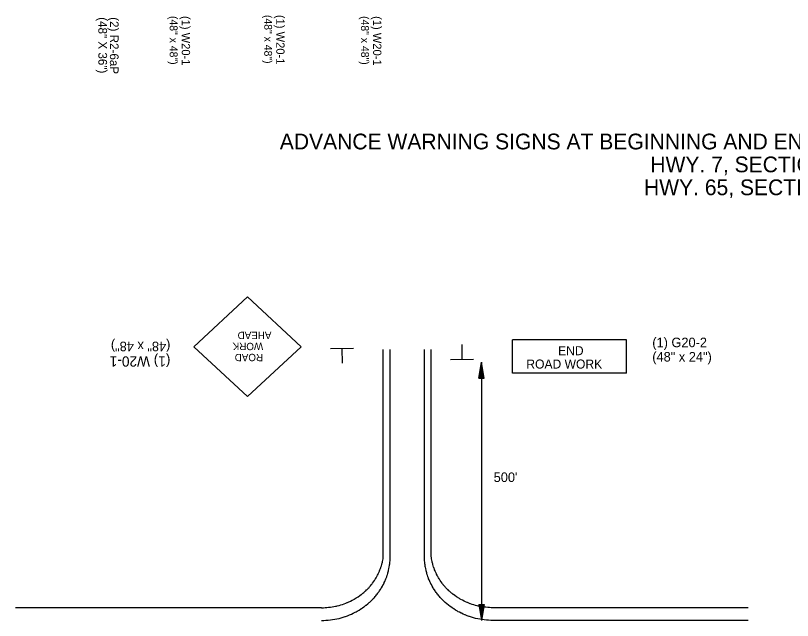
# Model space of a CAD drawing. Extents: x 32485 to 39285, y 55121 to 58033.
# Drawn here: x 37987 to 38508, y 56996 to 57401 of the extents above; entities that cross this region are included whole.
import ezdxf

# ---------------------------------------------------------------- set-up
doc = ezdxf.new("R2010")
doc.units = 0
for name, color, linetype in [('Default', 7, 'Continuous'), ('R_Border', 7, 'Continuous'), ('R_Draft', 7, 'Continuous'), ('R_Proposed Road', 7, 'Continuous'), ('SHET_Stamp-Prelim', 7, 'Continuous')]:
    doc.layers.add(name, color=color, linetype=linetype)

msp = doc.modelspace()

# ---------------------------------------------------------------- linework, layer by layer
at = {"layer": 'R_Border'}
for p, q in [((38106.85, 57178.9), (38142.77, 57212.26)), ((38142.77, 57212.26), (38178.71, 57178.9)), ((38396.7, 57183.42), (38320.4, 57183.42)), ((38320.4, 57161.14), (38320.4, 57183.42)), ((38396.7, 57161.14), (38396.7, 57183.42)), ((38106.85, 57178.9), (38142.77, 57145.5)), ((38142.77, 57145.5), (38178.71, 57178.9)), ((38286.54, 57170.46), (38286.5, 57180.3)), ((38198.26, 57177.77), (38213.78, 57178.01)), ((38205.98, 57177.68), (38206.16, 57167.84)), ((38294.27, 57170.28), (38278.75, 57170.21)), ((38396.7, 57161.14), (38320.4, 57161.14))]:
    msp.add_line(p, q, dxfattribs=at)
at = {"layer": 'R_Proposed Road'}
for p, q in [((38297.86, 57157.79), (38299.59, 57168.47)), ((38299.59, 57168.47), (38299.59, 56995.58)), ((38301.31, 57157.79), (38299.59, 57168.47)), ((38298.15, 57157.79), (38299.59, 57166.69)), ((38298.44, 57157.79), (38299.59, 57164.85)), ((38298.73, 57157.79), (38299.59, 57163.07)), ((38301.02, 57157.79), (38299.59, 57166.69)), ((38300.73, 57157.79), (38299.59, 57164.85)), ((38300.44, 57157.79), (38299.59, 57163.07)), ((38297.86, 57157.79), (38301.31, 57157.79)), ((38299.03, 57157.79), (38299.59, 57161.27)), ((38299.32, 57157.79), (38299.59, 57159.48)), ((38300.15, 57157.79), (38299.59, 57161.27)), ((38299.86, 57157.79), (38299.59, 57159.48)), ((38297.86, 57006.26), (38299.59, 56995.58)), ((38297.86, 57006.26), (38301.31, 57006.26)), ((38298.15, 57006.26), (38299.59, 56997.36)), ((38298.44, 57006.26), (38299.59, 56999.2)), ((38298.73, 57006.26), (38299.59, 57000.98)), ((38299.03, 57006.26), (38299.59, 57002.79)), ((38299.32, 57006.26), (38299.59, 57004.57)), ((38301.31, 57006.26), (38299.59, 56995.58)), ((38300.15, 57006.26), (38299.59, 57002.79)), ((38300.73, 57006.26), (38299.59, 56999.2)), ((38301.02, 57006.26), (38299.59, 56997.36)), ((38300.44, 57006.26), (38299.59, 57000.98)), ((38299.86, 57006.26), (38299.59, 57004.57))]:
    msp.add_line(p, q, dxfattribs=at)
at = {"layer": 'SHET_Stamp-Prelim'}
for p, q in [((38233.75, 57136.01), (38233.75, 57177.09)), ((38238.35, 57135.98), (38238.35, 57177.09)), ((38261.32, 57135.98), (38261.32, 57177.09)), ((38265.92, 57135.98), (38265.92, 57177.09))]:
    msp.add_line(p, q, dxfattribs=at)
for points in [[(38192.39, 56995.58), (38193.86, 56995.6), (38195.33, 56995.67), (38196.8, 56995.78), (38198.27, 56995.93), (38199.63, 56996.11), (38199.72, 56996.13), (38201.18, 56996.37), (38202.62, 56996.65), (38204.05, 56996.98), (38204.86, 56997.18), (38205.47, 56997.35), (38206.87, 56997.76), (38208.26, 56998.21), (38208.38, 56998.25), (38209.64, 56998.7), (38210.99, 56999.24), (38211.19, 56999.32), (38212.33, 56999.81), (38213.57, 57000.38), (38213.65, 57000.42), (38214.94, 57001.08), (38215.65, 57001.45), (38216.21, 57001.77), (38217.46, 57002.5), (38217.5, 57002.52), (38218.68, 57003.26), (38219.18, 57003.59), (38219.88, 57004.06), (38220.71, 57004.66), (38221.04, 57004.9), (38222.12, 57005.72), (38222.18, 57005.77), (38223.29, 57006.67), (38223.43, 57006.79), (38224.36, 57007.61), (38224.64, 57007.86), (38224.89, 57008.09), (38225.4, 57008.58), (38225.76, 57008.93), (38226.41, 57009.58), (38226.81, 57010), (38227.38, 57010.6), (38227.8, 57011.06), (38228.32, 57011.66), (38228.72, 57012.13), (38229.22, 57012.75), (38229.58, 57013.2), (38230.08, 57013.86), (38230.39, 57014.27), (38230.9, 57014.99), (38231.14, 57015.33), (38231.69, 57016.15), (38231.85, 57016.4), (38232.19, 57016.94), (38232.43, 57017.33), (38232.51, 57017.47), (38233.13, 57018.54), (38233.13, 57018.54), (38233.71, 57019.61), (38233.79, 57019.76), (38234.25, 57020.67), (38234.41, 57021), (38234.75, 57021.74), (38234.99, 57022.26), (38235.22, 57022.81), (38235.52, 57023.54), (38235.65, 57023.88), (38236, 57024.83), (38236.04, 57024.94), (38236.4, 57026.01), (38236.45, 57026.14), (38236.73, 57027.08), (38236.84, 57027.46), (38237.03, 57028.15), (38237.19, 57028.79), (38237.3, 57029.22), (38237.5, 57030.13), (38237.53, 57030.28), (38237.73, 57031.35), (38237.76, 57031.47), (38237.91, 57032.42), (38237.97, 57032.83), (38238.05, 57033.49), (38238.13, 57034.19), (38238.17, 57034.55), (38238.25, 57035.55), (38238.26, 57035.62), (38238.31, 57036.69), (38238.32, 57036.92), (38238.34, 57037.76), (38238.35, 57038.29), (38238.35, 57038.83), (38238.35, 57039.89), (38238.35, 57040.96), (38238.35, 57042.03), (38238.35, 57043.1), (38238.35, 57044.16), (38238.35, 57045.23), (38238.35, 57046.3), (38238.35, 57047.37), (38238.35, 57048.44), (38238.35, 57049.5), (38238.35, 57050.57), (38238.35, 57051.64), (38238.35, 57052.71), (38238.35, 57053.77), (38238.35, 57054.84), (38238.35, 57055.91), (38238.35, 57056.98), (38238.35, 57058.05), (38238.35, 57059.11), (38238.35, 57060.18), (38238.35, 57061.25), (38238.35, 57062.32), (38238.35, 57063.38), (38238.35, 57064.45), (38238.35, 57065.52), (38238.35, 57066.59), (38238.35, 57067.66), (38238.35, 57068.72), (38238.35, 57069.79), (38238.35, 57070.86), (38238.35, 57071.93), (38238.35, 57072.99), (38238.35, 57074.06), (38238.35, 57075.13), (38238.35, 57076.2), (38238.35, 57077.27), (38238.35, 57078.33), (38238.35, 57079.4), (38238.35, 57080.47), (38238.35, 57081.54), (38238.35, 57082.6), (38238.35, 57083.67), (38238.35, 57084.74), (38238.35, 57085.81), (38238.35, 57086.88), (38238.35, 57087.94), (38238.35, 57089.01), (38238.35, 57090.08), (38238.35, 57091.15), (38238.35, 57092.21), (38238.35, 57093.28), (38238.35, 57094.35), (38238.35, 57095.42), (38238.35, 57096.49), (38238.35, 57097.55), (38238.35, 57098.62), (38238.35, 57099.69), (38238.35, 57100.76), (38238.35, 57101.82), (38238.35, 57102.89), (38238.35, 57103.96), (38238.35, 57105.03), (38238.35, 57106.1), (38238.35, 57107.16), (38238.35, 57108.23), (38238.35, 57109.3), (38238.35, 57110.37), (38238.35, 57111.43), (38238.35, 57112.5), (38238.35, 57113.57), (38238.35, 57114.64), (38238.35, 57115.71), (38238.35, 57116.77), (38238.35, 57117.84), (38238.35, 57118.91), (38238.35, 57119.98), (38238.35, 57121.04), (38238.35, 57122.11), (38238.35, 57123.18), (38238.35, 57123.71), (38238.35, 57124.25), (38238.35, 57125.32), (38238.35, 57126.38), (38238.35, 57127.45), (38238.35, 57128.52), (38238.35, 57129.59), (38238.35, 57130.65), (38238.35, 57131.72), (38238.35, 57132.79), (38238.35, 57133.57), (38238.35, 57133.86), (38238.35, 57134.93), (38238.35, 57135.98)], [(38192.39, 57004.12), (38193.57, 57004.14), (38194.75, 57004.18), (38195.92, 57004.26), (38197.1, 57004.37), (38198.19, 57004.5), (38198.27, 57004.51), (38199.43, 57004.68), (38200.6, 57004.87), (38201.75, 57005.1), (38202.41, 57005.25), (38202.9, 57005.37), (38204.05, 57005.66), (38205.19, 57005.98), (38205.28, 57006.01), (38206.31, 57006.33), (38207.43, 57006.71), (38207.59, 57006.77), (38208.54, 57007.12), (38209.57, 57007.54), (38209.64, 57007.57), (38210.72, 57008.04), (38211.31, 57008.31), (38211.79, 57008.54), (38212.85, 57009.08), (38212.89, 57009.09), (38213.9, 57009.64), (38214.32, 57009.88), (38214.93, 57010.23), (38215.65, 57010.67), (38215.94, 57010.85), (38216.88, 57011.46), (38216.93, 57011.5), (38217.91, 57012.18), (38218.03, 57012.26), (38218.87, 57012.88), (38219.11, 57013.07), (38219.34, 57013.25), (38219.8, 57013.62), (38220.13, 57013.88), (38220.72, 57014.38), (38221.09, 57014.7), (38221.62, 57015.17), (38222, 57015.52), (38222.49, 57015.98), (38222.86, 57016.35), (38223.33, 57016.83), (38223.67, 57017.18), (38224.16, 57017.7), (38224.45, 57018.02), (38224.95, 57018.59), (38225.18, 57018.86), (38225.72, 57019.51), (38225.88, 57019.71), (38226.22, 57020.14), (38226.46, 57020.46), (38226.55, 57020.57), (38227.17, 57021.43), (38227.18, 57021.43), (38227.77, 57022.29), (38227.86, 57022.42), (38228.34, 57023.16), (38228.51, 57023.43), (38228.88, 57024.04), (38229.13, 57024.47), (38229.38, 57024.92), (38229.72, 57025.52), (38229.86, 57025.8), (38230.27, 57026.6), (38230.31, 57026.7), (38230.74, 57027.59), (38230.79, 57027.7), (38231.14, 57028.5), (38231.27, 57028.82), (38231.51, 57029.4), (38231.72, 57029.95), (38231.85, 57030.32), (38232.12, 57031.1), (38232.17, 57031.23), (38232.46, 57032.16), (38232.5, 57032.27), (38232.73, 57033.09), (38232.83, 57033.45), (38232.97, 57034.02), (38233.12, 57034.64), (38233.19, 57034.96), (38233.37, 57035.85), (38233.38, 57035.91), (38233.55, 57036.86), (38233.58, 57037.06), (38233.69, 57037.81), (38233.75, 57038.29), (38233.75, 57038.83), (38233.75, 57039.89), (38233.75, 57040.96), (38233.75, 57042.03), (38233.75, 57043.1), (38233.75, 57044.16), (38233.75, 57045.23), (38233.75, 57046.3), (38233.75, 57047.37), (38233.75, 57048.44), (38233.75, 57049.5), (38233.75, 57050.57), (38233.75, 57051.64), (38233.75, 57052.71), (38233.75, 57053.77), (38233.75, 57054.84), (38233.75, 57055.91), (38233.75, 57056.98), (38233.75, 57058.05), (38233.75, 57059.11), (38233.75, 57060.18), (38233.75, 57061.25), (38233.75, 57062.32), (38233.75, 57063.38), (38233.75, 57064.45), (38233.75, 57065.52), (38233.75, 57066.59), (38233.75, 57067.66), (38233.75, 57068.72), (38233.75, 57069.79), (38233.75, 57070.86), (38233.75, 57071.93), (38233.75, 57072.99), (38233.75, 57074.06), (38233.75, 57075.13), (38233.75, 57076.2), (38233.75, 57077.27), (38233.75, 57078.33), (38233.75, 57079.4), (38233.75, 57080.47), (38233.75, 57081.54), (38233.75, 57082.6), (38233.75, 57083.67), (38233.75, 57084.74), (38233.75, 57085.81), (38233.75, 57086.88), (38233.75, 57087.94), (38233.75, 57089.01), (38233.75, 57090.08), (38233.75, 57091.15), (38233.75, 57092.21), (38233.75, 57093.28), (38233.75, 57094.35), (38233.75, 57095.42), (38233.75, 57096.49), (38233.75, 57097.55), (38233.75, 57098.62), (38233.75, 57099.69), (38233.75, 57100.76), (38233.75, 57101.82), (38233.75, 57102.89), (38233.75, 57103.96), (38233.75, 57105.03), (38233.75, 57106.1), (38233.75, 57107.16), (38233.75, 57108.23), (38233.75, 57109.3), (38233.75, 57110.37), (38233.75, 57111.43), (38233.75, 57112.5), (38233.75, 57113.57), (38233.75, 57114.64), (38233.75, 57115.71), (38233.75, 57116.77), (38233.75, 57117.84), (38233.75, 57118.91), (38233.75, 57119.98), (38233.75, 57121.04), (38233.75, 57122.11), (38233.75, 57123.18), (38233.75, 57123.71), (38233.75, 57124.25), (38233.75, 57125.32), (38233.75, 57126.38), (38233.75, 57127.45), (38233.75, 57128.52), (38233.75, 57129.59), (38233.75, 57130.65), (38233.75, 57131.72), (38233.75, 57132.79), (38233.75, 57133.57), (38233.75, 57133.86), (38233.75, 57134.94), (38233.75, 57135.98)], [(38307.28, 56995.58), (38305.8, 56995.6), (38304.33, 56995.67), (38302.86, 56995.78), (38301.4, 56995.93), (38300.03, 56996.11), (38299.94, 56996.13), (38298.49, 56996.37), (38297.05, 56996.65), (38295.62, 56996.98), (38294.81, 56997.18), (38294.2, 56997.35), (38292.8, 56997.76), (38291.41, 56998.21), (38291.29, 56998.25), (38290.03, 56998.7), (38288.68, 56999.24), (38288.48, 56999.32), (38287.34, 56999.81), (38286.1, 57000.38), (38286.02, 57000.42), (38284.73, 57001.08), (38284.02, 57001.45), (38283.45, 57001.77), (38282.21, 57002.5), (38282.17, 57002.52), (38280.99, 57003.26), (38280.49, 57003.59), (38279.79, 57004.06), (38278.95, 57004.66), (38278.62, 57004.9), (38277.55, 57005.72), (38277.49, 57005.77), (38276.38, 57006.67), (38276.24, 57006.79), (38275.31, 57007.61), (38275.03, 57007.86), (38274.78, 57008.09), (38274.27, 57008.58), (38273.91, 57008.93), (38273.26, 57009.58), (38272.85, 57010), (38272.29, 57010.6), (38271.87, 57011.06), (38271.35, 57011.66), (38270.95, 57012.13), (38270.45, 57012.75), (38270.09, 57013.2), (38269.59, 57013.86), (38269.28, 57014.27), (38268.76, 57014.99), (38268.53, 57015.33), (38267.98, 57016.15), (38267.82, 57016.4), (38267.48, 57016.94), (38267.24, 57017.33), (38267.15, 57017.47), (38266.53, 57018.54), (38266.53, 57018.54), (38265.95, 57019.61), (38265.87, 57019.76), (38265.41, 57020.67), (38265.26, 57021), (38264.91, 57021.74), (38264.68, 57022.26), (38264.45, 57022.81), (38264.15, 57023.54), (38264.02, 57023.88), (38263.66, 57024.83), (38263.62, 57024.94), (38263.26, 57026.01), (38263.22, 57026.14), (38262.93, 57027.08), (38262.83, 57027.46), (38262.64, 57028.15), (38262.47, 57028.79), (38262.37, 57029.22), (38262.17, 57030.13), (38262.14, 57030.28), (38261.93, 57031.35), (38261.91, 57031.47), (38261.76, 57032.42), (38261.7, 57032.83), (38261.61, 57033.49), (38261.53, 57034.19), (38261.5, 57034.55), (38261.42, 57035.55), (38261.41, 57035.62), (38261.35, 57036.69), (38261.35, 57036.92), (38261.33, 57037.76), (38261.32, 57038.29), (38261.32, 57038.83), (38261.32, 57039.89), (38261.32, 57040.96), (38261.32, 57042.03), (38261.32, 57043.1), (38261.32, 57044.16), (38261.32, 57045.23), (38261.32, 57046.3), (38261.32, 57047.37), (38261.32, 57048.44), (38261.32, 57049.5), (38261.32, 57050.57), (38261.32, 57051.64), (38261.32, 57052.71), (38261.32, 57053.77), (38261.32, 57054.84), (38261.32, 57055.91), (38261.32, 57056.98), (38261.32, 57058.05), (38261.32, 57059.11), (38261.32, 57060.18), (38261.32, 57061.25), (38261.32, 57062.32), (38261.32, 57063.38), (38261.32, 57064.45), (38261.32, 57065.52), (38261.32, 57066.59), (38261.32, 57067.66), (38261.32, 57068.72), (38261.32, 57069.79), (38261.32, 57070.86), (38261.32, 57071.93), (38261.32, 57072.99), (38261.32, 57074.06), (38261.32, 57075.13), (38261.32, 57076.2), (38261.32, 57077.27), (38261.32, 57078.33), (38261.32, 57079.4), (38261.32, 57080.47), (38261.32, 57081.54), (38261.32, 57082.6), (38261.32, 57083.67), (38261.32, 57084.74), (38261.32, 57085.81), (38261.32, 57086.88), (38261.32, 57087.94), (38261.32, 57089.01), (38261.32, 57090.08), (38261.32, 57091.15), (38261.32, 57092.21), (38261.32, 57093.28), (38261.32, 57094.35), (38261.32, 57095.42), (38261.32, 57096.49), (38261.32, 57097.55), (38261.32, 57098.62), (38261.32, 57099.69), (38261.32, 57100.76), (38261.32, 57101.82), (38261.32, 57102.89), (38261.32, 57103.96), (38261.32, 57105.03), (38261.32, 57106.1), (38261.32, 57107.16), (38261.32, 57108.23), (38261.32, 57109.3), (38261.32, 57110.37), (38261.32, 57111.43), (38261.32, 57112.5), (38261.32, 57113.57), (38261.32, 57114.64), (38261.32, 57115.71), (38261.32, 57116.77), (38261.32, 57117.84), (38261.32, 57118.91), (38261.32, 57119.98), (38261.32, 57121.04), (38261.32, 57122.11), (38261.32, 57123.18), (38261.32, 57123.71), (38261.32, 57124.25), (38261.32, 57125.32), (38261.32, 57126.38), (38261.32, 57127.45), (38261.32, 57128.52), (38261.32, 57129.59), (38261.32, 57130.65), (38261.32, 57131.72), (38261.32, 57132.79), (38261.32, 57133.57), (38261.32, 57133.86), (38261.32, 57134.92), (38261.32, 57135.98)], [(38307.28, 57004.12), (38306.1, 57004.14), (38304.92, 57004.18), (38303.74, 57004.26), (38302.57, 57004.37), (38301.47, 57004.5), (38301.4, 57004.51), (38300.23, 57004.68), (38299.07, 57004.87), (38297.91, 57005.1), (38297.26, 57005.25), (38296.76, 57005.37), (38295.62, 57005.66), (38294.48, 57005.98), (38294.38, 57006.01), (38293.35, 57006.33), (38292.24, 57006.71), (38292.07, 57006.77), (38291.13, 57007.12), (38290.1, 57007.54), (38290.03, 57007.57), (38288.95, 57008.04), (38288.35, 57008.31), (38287.87, 57008.54), (38286.82, 57009.08), (38286.78, 57009.09), (38285.77, 57009.64), (38285.34, 57009.88), (38284.74, 57010.23), (38284.02, 57010.67), (38283.73, 57010.85), (38282.79, 57011.46), (38282.74, 57011.5), (38281.76, 57012.18), (38281.63, 57012.26), (38280.8, 57012.88), (38280.55, 57013.07), (38280.33, 57013.25), (38279.86, 57013.62), (38279.54, 57013.88), (38278.95, 57014.38), (38278.58, 57014.7), (38278.05, 57015.17), (38277.67, 57015.52), (38277.18, 57015.98), (38276.81, 57016.35), (38276.33, 57016.83), (38275.99, 57017.18), (38275.51, 57017.7), (38275.22, 57018.02), (38274.72, 57018.59), (38274.48, 57018.86), (38273.95, 57019.51), (38273.78, 57019.71), (38273.45, 57020.14), (38273.21, 57020.46), (38273.12, 57020.57), (38272.49, 57021.43), (38272.49, 57021.43), (38271.89, 57022.29), (38271.81, 57022.42), (38271.33, 57023.16), (38271.16, 57023.43), (38270.79, 57024.04), (38270.54, 57024.47), (38270.28, 57024.92), (38269.95, 57025.52), (38269.8, 57025.8), (38269.4, 57026.6), (38269.35, 57026.7), (38268.93, 57027.59), (38268.88, 57027.7), (38268.53, 57028.5), (38268.4, 57028.82), (38268.16, 57029.4), (38267.95, 57029.95), (38267.82, 57030.32), (38267.54, 57031.1), (38267.5, 57031.23), (38267.2, 57032.16), (38267.17, 57032.27), (38266.94, 57033.09), (38266.84, 57033.45), (38266.69, 57034.02), (38266.55, 57034.64), (38266.48, 57034.96), (38266.3, 57035.85), (38266.29, 57035.91), (38266.12, 57036.86), (38266.09, 57037.06), (38265.98, 57037.81), (38265.92, 57038.29), (38265.92, 57038.83), (38265.92, 57039.89), (38265.92, 57040.96), (38265.92, 57042.03), (38265.92, 57043.1), (38265.92, 57044.16), (38265.92, 57045.23), (38265.92, 57046.3), (38265.92, 57047.37), (38265.92, 57048.44), (38265.92, 57049.5), (38265.92, 57050.57), (38265.92, 57051.64), (38265.92, 57052.71), (38265.92, 57053.77), (38265.92, 57054.84), (38265.92, 57055.91), (38265.92, 57056.98), (38265.92, 57058.05), (38265.92, 57059.11), (38265.92, 57060.18), (38265.92, 57061.25), (38265.92, 57062.32), (38265.92, 57063.38), (38265.92, 57064.45), (38265.92, 57065.52), (38265.92, 57066.59), (38265.92, 57067.66), (38265.92, 57068.72), (38265.92, 57069.79), (38265.92, 57070.86), (38265.92, 57071.93), (38265.92, 57072.99), (38265.92, 57074.06), (38265.92, 57075.13), (38265.92, 57076.2), (38265.92, 57077.27), (38265.92, 57078.33), (38265.92, 57079.4), (38265.92, 57080.47), (38265.92, 57081.54), (38265.92, 57082.6), (38265.92, 57083.67), (38265.92, 57084.74), (38265.92, 57085.81), (38265.92, 57086.88), (38265.92, 57087.94), (38265.92, 57089.01), (38265.92, 57090.08), (38265.92, 57091.15), (38265.92, 57092.21), (38265.92, 57093.28), (38265.92, 57094.35), (38265.92, 57095.42), (38265.92, 57096.49), (38265.92, 57097.55), (38265.92, 57098.62), (38265.92, 57099.69), (38265.92, 57100.76), (38265.92, 57101.82), (38265.92, 57102.89), (38265.92, 57103.96), (38265.92, 57105.03), (38265.92, 57106.1), (38265.92, 57107.16), (38265.92, 57108.23), (38265.92, 57109.3), (38265.92, 57110.37), (38265.92, 57111.43), (38265.92, 57112.5), (38265.92, 57113.57), (38265.92, 57114.64), (38265.92, 57115.71), (38265.92, 57116.77), (38265.92, 57117.84), (38265.92, 57118.91), (38265.92, 57119.98), (38265.92, 57121.04), (38265.92, 57122.11), (38265.92, 57123.18), (38265.92, 57123.71), (38265.92, 57124.25), (38265.92, 57125.32), (38265.92, 57126.38), (38265.92, 57127.45), (38265.92, 57128.52), (38265.92, 57129.59), (38265.92, 57130.65), (38265.92, 57131.72), (38265.92, 57132.79), (38265.92, 57133.57), (38265.92, 57133.86), (38265.92, 57134.92), (38265.92, 57135.98), (38265.92, 57135.98)], [(38192.39, 57004.12), (38186.65, 57004.12), (38175.16, 57004.12), (38163.67, 57004.12), (38152.18, 57004.12), (38140.69, 57004.12), (38129.2, 57004.12), (38120.03, 57004.12), (38117.71, 57004.12), (38106.23, 57004.12), (38094.74, 57004.12), (38083.25, 57004.12), (38071.76, 57004.12), (38060.27, 57004.12), (38048.78, 57004.12), (38037.29, 57004.12), (38035.87, 57004.12), (38025.8, 57004.12), (38014.32, 57004.12), (38002.83, 57004.12), (37991.34, 57004.12), (37987.24, 57004.12)], [(38478.26, 57004.12), (38473.86, 57004.12), (38462.37, 57004.12), (38450.89, 57004.12), (38439.4, 57004.12), (38427.91, 57004.12), (38416.42, 57004.12), (38404.93, 57004.12), (38393.44, 57004.12), (38381.95, 57004.12), (38372.51, 57004.12), (38372.51, 57004.12), (38370.46, 57004.12), (38358.98, 57004.12), (38347.49, 57004.12), (38336, 57004.12), (38324.51, 57004.12), (38313.02, 57004.12), (38307.28, 57004.12)], [(38478.26, 56995.58), (38473.86, 56995.58), (38462.37, 56995.58), (38450.89, 56995.58), (38439.4, 56995.58), (38427.91, 56995.58), (38416.42, 56995.58), (38404.93, 56995.58), (38393.44, 56995.58), (38381.95, 56995.58), (38372.51, 56995.58), (38372.51, 56995.58), (38370.46, 56995.58), (38358.98, 56995.58), (38347.49, 56995.58), (38336, 56995.58), (38324.51, 56995.58), (38313.02, 56995.58), (38307.28, 56995.58)]]:
    msp.add_lwpolyline(points, dxfattribs=at)

# ---------------------------------------------------------------- texts
at = {"layer": 'Default'}
for s, p in [('ADVANCE WARNING SIGNS AT BEGINNING AND END OF WORK ZONE', (38164.36, 57311.07)), ('HWY. 7, SECTION 18', (38412.73, 57295.73)), ('HWY. 65, SECTION 7', (38408.47, 57280.4))]:
    msp.add_text(s, height=10.5571, dxfattribs=at).set_placement(p)
at = {"layer": 'R_Border'}
for s, height, rotation, p in [('(48" x 48")', 5.2332, 270, (38090.61, 57400.44)), ('(1) W20-1', 5.583, 270, (38098.64, 57400.44)), ('(48" x 48")', 5.2332, 270, (38153.96, 57401.14)), ('(1) W20-1', 5.583, 270, (38161.99, 57401.14)), ('(48" x 48")', 5.2332, 270, (38218.85, 57400.35)), ('(1) W20-1', 5.583, 270, (38226.89, 57400.35)), (' AHEAD ', 4.92, 180.0005, (38160.59, 57188.9)), ('(48" x 48")', 6.406, 180, (38091.04, 57182.27)), ('WORK', 4.919, 180, (38153.26, 57181.52)), ('(1) W20-1', 6.834, 180, (38091.04, 57172.44)), ('ROAD', 4.92, 180.0004, (38153.15, 57174.14))]:
    msp.add_text(s, height=height, rotation=rotation, dxfattribs=at).set_placement(p)
for s, height, p in [('(1) G20-2', 6.407, (38414.03, 57178.58)), ('END', 6.054, (38350.9, 57173.22)), ('(48" x 24")', 6.406, (38414.03, 57168.98)), ('ROAD WORK', 6.054, (38329.63, 57164.28))]:
    msp.add_text(s, height=height, dxfattribs=at).set_placement(p)
at = {"layer": 'R_Draft'}
for s, height, p in [('(48" X 36")', 5.8301, (38042.76, 57399.6)), ('(2) R2-6aP', 5.83, (38050.49, 57399.6))]:
    msp.add_text(s, height=height, rotation=270, dxfattribs=at).set_placement(p)
at = {"layer": 'R_Proposed Road'}
msp.add_text("500'", height=6.407, dxfattribs=at).set_placement((38307.73, 57088.31))

doc.saveas('drawing.dxf')
